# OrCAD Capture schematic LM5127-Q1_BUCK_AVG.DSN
size Custom; title: LM5127-Q1 2.2MHz Wide VIN Automotive Front-stage; rev: 1.0; note: Datasheet: NA     EVM: NA; note: Synchronous Step Down Converter
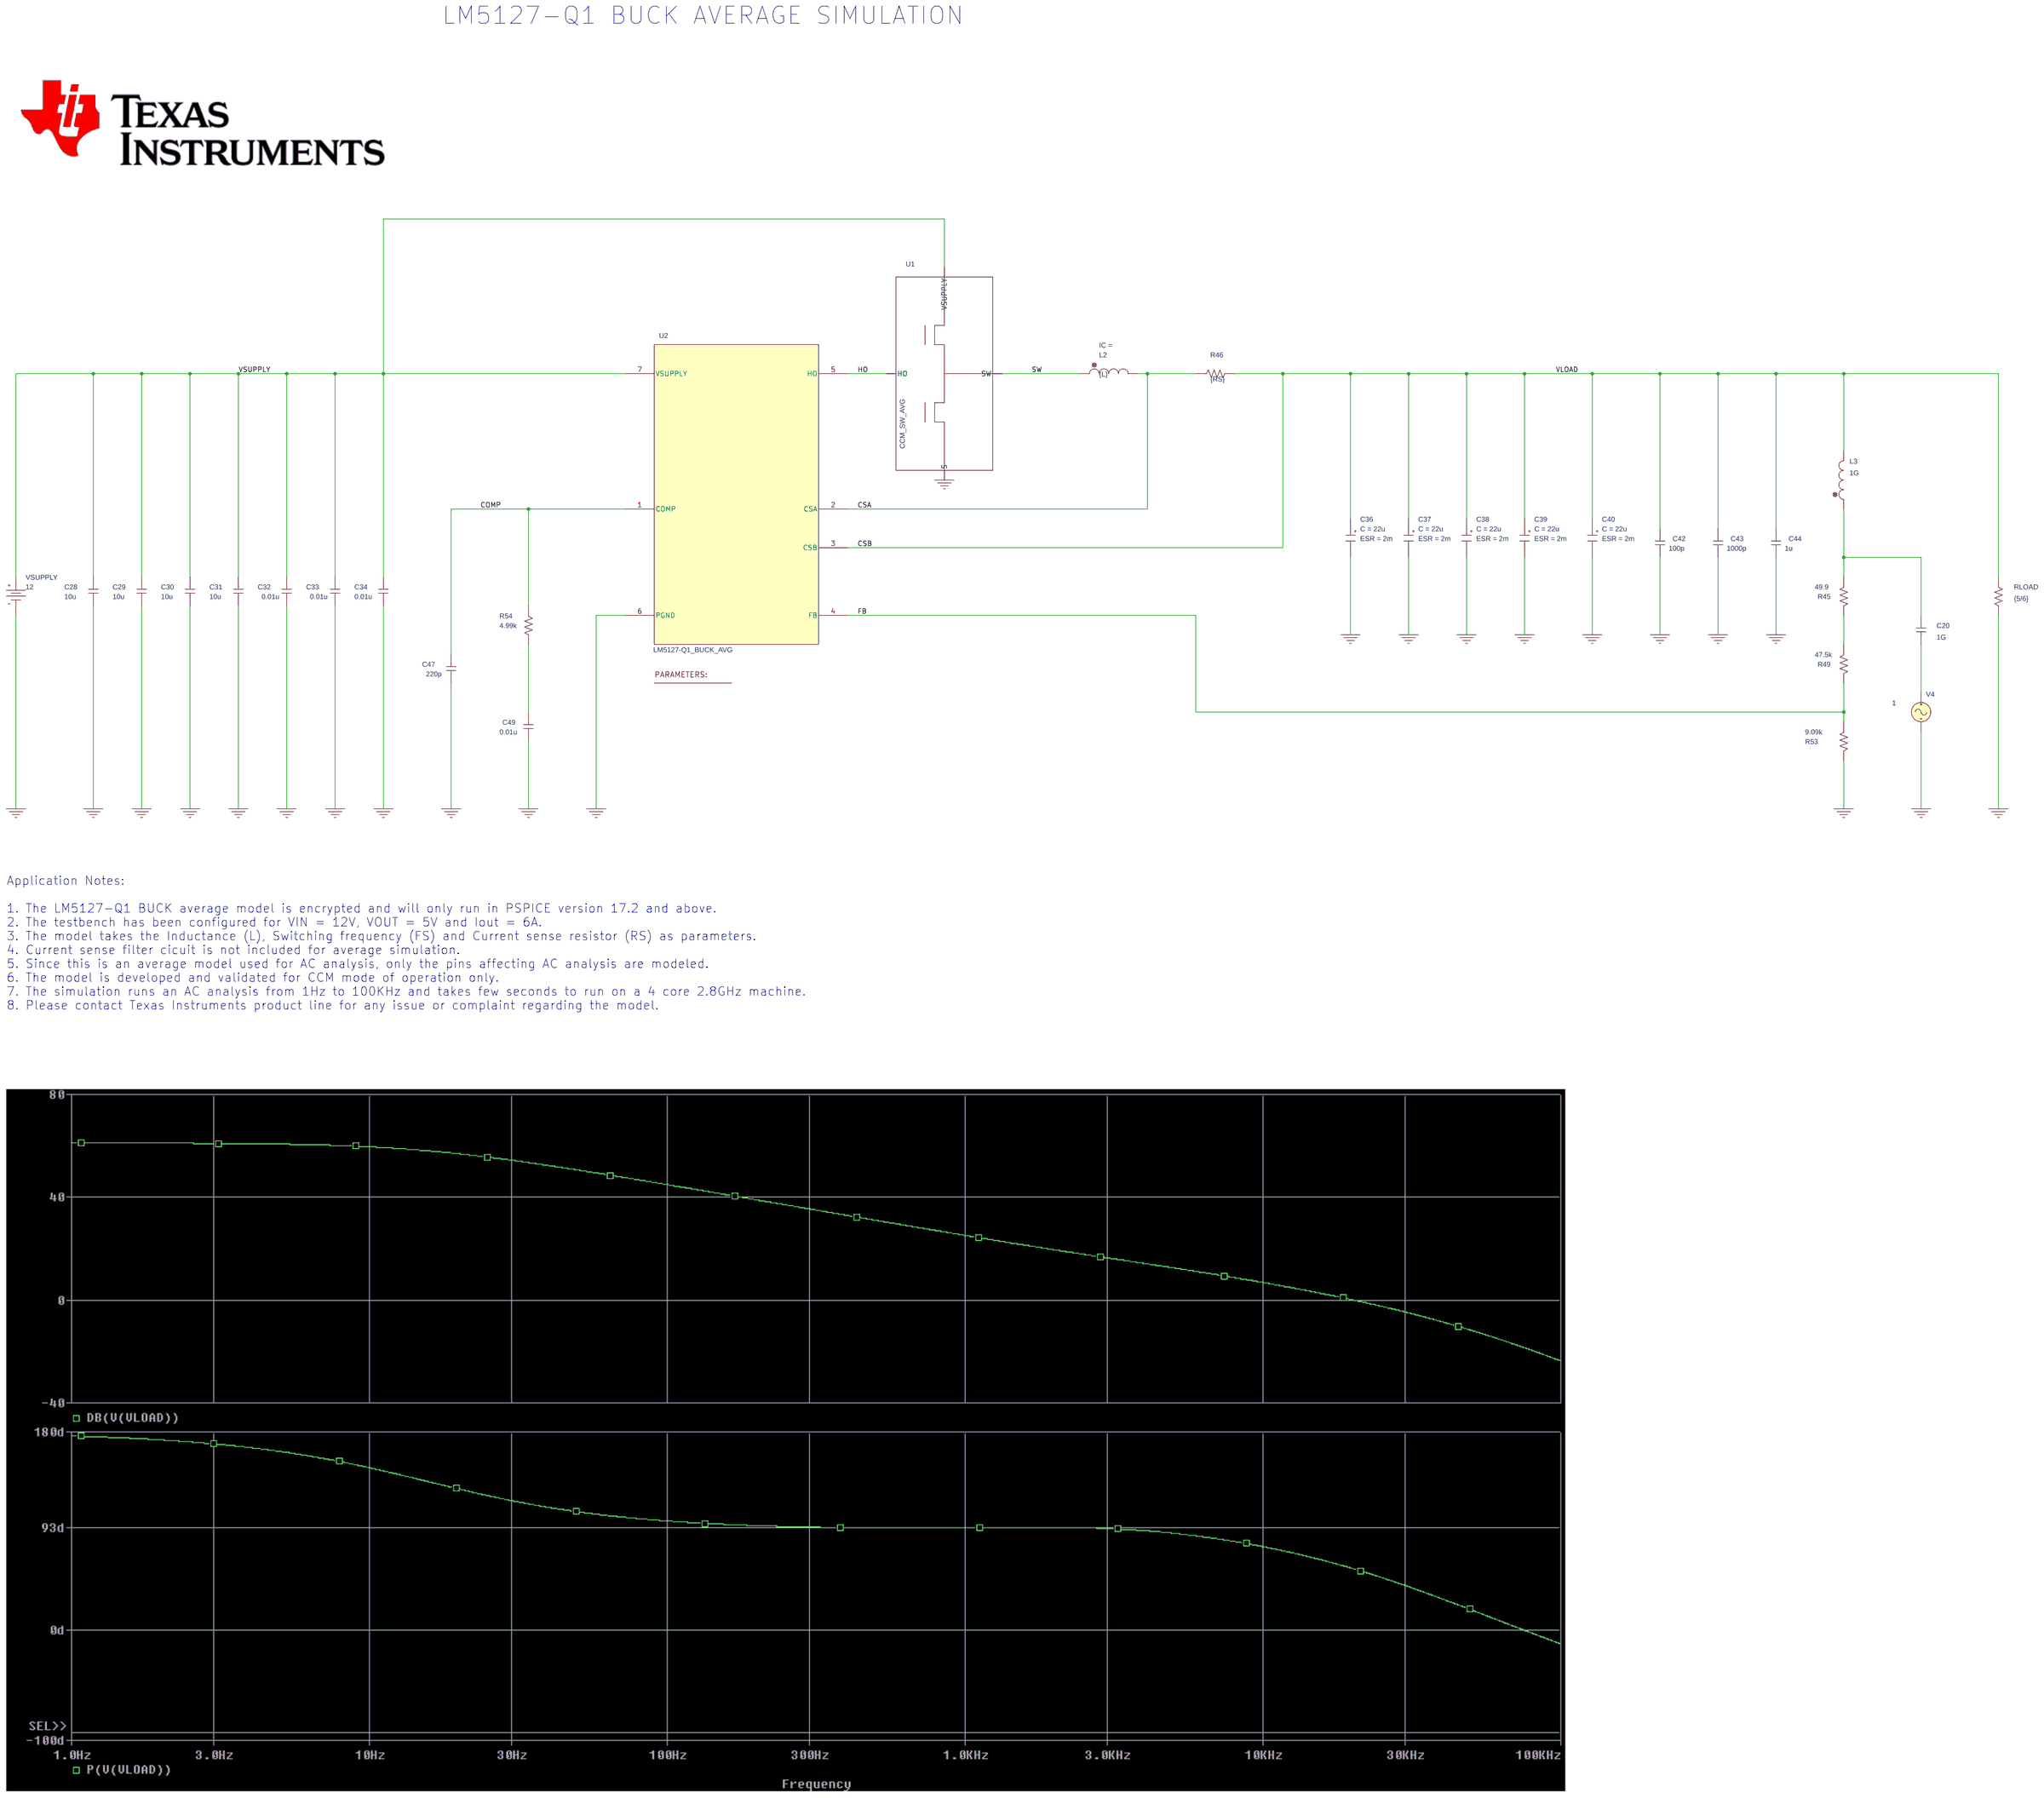
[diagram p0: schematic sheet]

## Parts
1  PARAM
C20  1G  [RAD/CK05]
C28  10u  [RAD/CK05]
C29  10u  [RAD/CK05]
C30  10u  [RAD/CK05]
C31  10u  [RAD/CK05]
C32  0.01u  [RAD/CK05]
C33  0.01u  [RAD/CK05]
C34  0.01u  [RAD/CK05]
C36  CESR
C37  CESR
C38  CESR
C39  CESR
C40  CESR
C42  100p  [RAD/CK05]
C43  1000p  [RAD/CK05]
C44  1u  [RAD/CK05]
C47  220p  [RAD/CK05]
C49  0.01u  [RAD/CK05]
L2  {L}  [DISC/.350x.175/LS.200x.100/.034]
L3  1G  [DISC/.350x.175/LS.200x.100/.034]
R45  49.9  [AX/RC05]
R46  {RS}  [AX/RC05]
R49  47.5k  [AX/RC05]
R53  9.09k  [AX/RC05]
R54  4.99k  [AX/RC05]
RLOAD  {5/6}  [AX/RC05]
U1  CCM_SW_AVG  [DRB0008A]
U2  LM5127-Q1_BUCK_AVG
V4  VAC
VSUPPLY  VDC

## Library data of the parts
1 = PARAM: FS: 440k; L: 2.4u; RS: 5m
C20 C28-C34 C42-C44 C47 C49 = C
C36-C40 = CESR_0: C: 22u; ESR: 2m; PSpiceTemplate: X^@REFDES %IN %OUT @MODEL PARAMS:  ?C|C=@C||C=100u|  ?ESR|ESR=@ESR||ESR=0.01|; X: 1
L2 L3 = L
R45 R46 R49 R53 R54 RLOAD = R
U1 = CCM_SW_AVG
U2 = LM5127-Q1_BUCK_AVG
V4 = VAC: ACMAG: 1; ACPHASE: 0
VSUPPLY = VDC: DC: 12

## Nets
0: C28.2 C29.2 C30.2 C31.2 C32.2 C33.2 C34.2 C36.2(OUT) C37.2(OUT) C38.2(OUT) C39.2(OUT) C40.2(OUT) C42.2 C43.2 C44.2 C47.2 C49.2 R53.2 RLOAD.2 U1.S U2.6(PGND) V4.2(-) VSUPPLY.1(-)
COMP: C47.1 R54.1 U2.1(COMP)
CSA: L2.2 R46.1 U2.2(CSA)
CSB: C36.1(IN) C37.1(IN) C38.1(IN) C39.1(IN) C40.1(IN) C42.1 C43.1 C44.1 L3.2 R46.2 RLOAD.1 U2.3(CSB)
FB: R49.2 R53.1 U2.4(FB)
HO: U1.HO U2.5(HO)
SW: L2.1 U1.SW
VSUPPLY: C28.1 C29.1 C30.1 C31.1 C32.1 C33.1 C34.1 U1.VSUPPLY U2.7(VSUPPLY) VSUPPLY.0(+)
N307172: C49.1 R54.2
N311691: R45.2 R49.1
N16772710: C20.1 L3.1 R45.1
N16772752: C20.2 V4.1(+)

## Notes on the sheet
- LM5127-Q1 BUCK AVERAGE SIMULATION
- Application Notes:
  1. The LM5127-Q1 BUCK average model is encrypted and will only run in PSPICE version 17.2 and above.
  2. The testbench has been configured for VIN = 12V, VOUT = 5V and Iout = 6A.
  3. The model takes the Inductance (L), Switching frequency (FS) and Current sense resistor (RS) as parameters.
  4. Current sense filter cicuit is not included for average simulation.
  5. Since this is an average model used for AC analysis, only the pins affecting AC analysis are modeled.
  6. The model is developed and validated for CCM mode of operation only.
  7. The simulation runs an AC analysis from 1Hz to 100KHz and takes few seconds to run on a 4 core 2.8GHz machine.
  8. Please contact Texas Instruments product line for any issue or complaint regarding the model.
